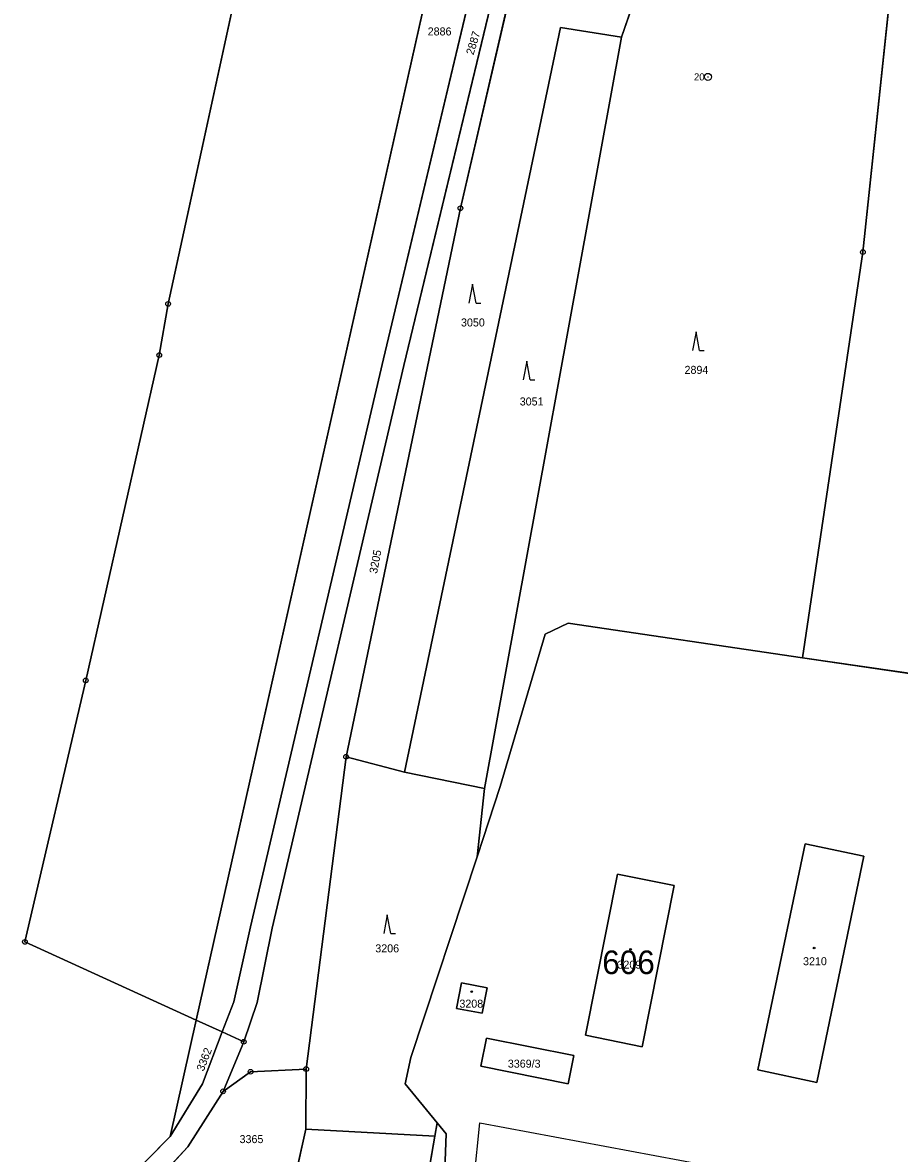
# Model space of a CAD drawing. Extents: x -689422 to -685210, y -987725 to -982160.
# Drawn here: x -688196.3 to -688010, y -986923.9 to -986683.7 of the extents above; entities that cross this region are included whole.
import ezdxf

# ---------------------------------------------------------------- set-up
doc = ezdxf.new("R2010")
doc.units = 0
for name, color, linetype in [('KN_Budovy', 7, 'Continuous'), ('KN_Budovy_cisla_domovni', 7, 'Continuous'), ('KN_Hranice_parcel', 7, 'Continuous'), ('KN_Hranice_parcel_vnitrni_kresba', 7, 'Continuous'), ('KN_Parcelni cisla', 7, 'Continuous'), ('KN_Polygon parcely', 7, 'Continuous'), ('KN_POZEMKY_LESNI POZEMEK', 7, 'Continuous'), ('KN_POZEMKY_ORNA PUDA', 7, 'Continuous'), ('KN_POZEMKY_OSTATNI PLOCHA', 7, 'Continuous'), ('KN_POZEMKY_ZASTAVENA PLOCHA', 7, 'Continuous'), ('KN_VYUZITI_17_ostatni plocha_ostatni komunikace', 7, 'Continuous'), ('KN_VYUZITI_23_ostatni plocha_manipulacni plocha', 7, 'Continuous'), ('KN_VYUZITI_26_ostatni plocha_jina plocha', 7, 'Continuous'), ('KN_Značky bodu BP', 7, 'Continuous'), ('KN_Značky budov', 7, 'Continuous'), ('KN_Značky kultur', 7, 'Continuous')]:
    doc.layers.add(name, color=color, linetype=linetype)

msp = doc.modelspace()

# ---------------------------------------------------------------- linework, layer by layer
at = {"layer": 'KN_Budovy'}
for points in [[(-688027.49, -986908.86), (-688017.55, -986860.75), (-688030.03, -986858.17), (-688040.05, -986906.21)], [(-688069.91, -986864.6), (-688076.68, -986898.8), (-688064.67, -986901.32), (-688057.85, -986866.99)], [(-688103.01, -986887.69), (-688104.12, -986893.15), (-688098.66, -986894.12), (-688097.6, -986888.77)]]:
    msp.add_lwpolyline(points, close=True, dxfattribs=at)
at = {"layer": 'KN_Hranice_parcel'}
for p, q in [((-688159.4, -986895.61), (-688054.13, -986426.81)), ((-688063.02, -986669.39), (-688069.02, -986686.77)), ((-688011.67, -986674.75), (-688017.74, -986732.42)), ((-688069.02, -986686.77), (-688098.17, -986846.39)), ((-688017.74, -986732.42), (-688030.54, -986818.6)), ((-688080.39, -986811.27), (-688030.54, -986818.6)), ((-688030.54, -986818.6), (-687921.47, -986834.64)), ((-688127.55, -986839.67), (-688136.03, -986906.02)), ((-688127.55, -986839.67), (-688115.17, -986842.96)), ((-688115.17, -986842.96), (-688098.17, -986846.39)), ((-688099.71, -986860.89), (-688094.78, -986845.97)), ((-688098.17, -986846.39), (-688099.71, -986860.89)), ((-688113.79, -986903.54), (-688099.71, -986860.89)), ((-688164.95, -986920.32), (-688159.4, -986895.61)), ((-688159.4, -986895.61), (-688153.85, -986898.14)), ((-688153.85, -986898.14), (-688149.3, -986900.22)), ((-688149.3, -986900.22), (-688153.68, -986910.75)), ((-688136.03, -986906.02), (-688136.11, -986918.82)), ((-688108.67, -986920.25), (-688108.19, -986917.45)), ((-688136.11, -986918.82), (-688108.67, -986920.25)), ((-688108.67, -986920.25), (-688122.47, -987000.06))]:
    msp.add_line(p, q, dxfattribs=at)
for points in [[(-688159.4, -986895.61), (-688195.78, -986878.99), (-688182.85, -986823.42), (-688167.24, -986754.29), (-688165.37, -986743.42), (-688139.35, -986623.85), (-688109.82, -986514.74), (-688083.69, -986418.21), (-688054.13, -986426.81)], [(-688153.85, -986898.14), (-688151.4, -986891.74), (-688147.87, -986875.77), (-688119.62, -986755.13), (-688100.96, -986676.85), (-688080.88, -986596.53), (-688070.98, -986551.86), (-688053.37, -986481.38), (-688042.32, -986437.91), (-688040.63, -986430.74)], [(-688149.3, -986900.22), (-688146.47, -986891.87), (-688143.27, -986876.11), (-688115.31, -986756.51), (-688096.35, -986678.03), (-688076.79, -986597.87), (-688066.92, -986553.28), (-688049.47, -986482.89), (-688036.65, -986431.9)], [(-688089.54, -986664.62), (-688091, -986670.24), (-688103.26, -986723.09), (-688127.55, -986839.67)], [(-688115.17, -986842.96), (-688082.01, -986684.71), (-688069.02, -986686.77)], [(-688094.78, -986845.97), (-688085.26, -986813.61), (-688080.39, -986811.27)], [(-688017.55, -986860.75), (-688030.03, -986858.17), (-688040.05, -986906.21), (-688027.49, -986908.86), (-688017.55, -986860.75)], [(-688064.67, -986901.32), (-688057.85, -986866.99), (-688069.91, -986864.6), (-688076.68, -986898.8), (-688064.67, -986901.32)], [(-688103.01, -986887.69), (-688104.12, -986893.15), (-688098.66, -986894.12), (-688097.6, -986888.77), (-688103.01, -986887.69)], [(-688164.95, -986920.32), (-688158.09, -986909.19), (-688153.85, -986898.14)], [(-688097.69, -986899.48), (-688098.9, -986905.4), (-688080.34, -986909.15), (-688079.13, -986903.11), (-688097.69, -986899.48)], [(-688108.19, -986917.45), (-688114.98, -986909.18), (-688113.79, -986903.54)], [(-688153.68, -986910.75), (-688147.85, -986906.59), (-688136.03, -986906.02)], [(-688189.3, -986941.47), (-688172.33, -986934.61), (-688161.2, -986922.54), (-688153.68, -986910.75)], [(-688115.39, -987004.23), (-688107.71, -986957.91), (-688106.29, -986919.76), (-688108.19, -986917.45)], [(-688193.03, -986937.49), (-688175.31, -986930.89), (-688164.95, -986920.32)], [(-688144.21, -986962.1), (-688141.1, -986941.33), (-688136.11, -986918.82)]]:
    msp.add_lwpolyline(points, dxfattribs=at)
at = {"layer": 'KN_Hranice_parcel_vnitrni_kresba'}
for p, q in [((-688108.07, -987008.55), (-688099.13, -986917.41)), ((-688099.13, -986917.41), (-687943.29, -986946.49))]:
    msp.add_line(p, q, dxfattribs=at)
at = {"layer": 'KN_Polygon parcely'}
for points in [[(-688175.31, -986930.89), (-688164.95, -986920.32), (-688159.4, -986895.61), (-688195.78, -986878.99), (-688182.85, -986823.42), (-688167.24, -986754.29), (-688165.37, -986743.42), (-688139.35, -986623.85), (-688109.82, -986514.74), (-688083.69, -986418.21), (-688054.13, -986426.81), (-687983.51, -986112.31), (-687977.17, -986084.07), (-687905.28, -985782.43)], [(-687738.9, -987010.24), (-687777.85, -986868.06), (-687801.59, -986853.04), (-687857.29, -986844.48), (-687917.71, -986835.19), (-687921.47, -986834.64), (-688030.54, -986818.6), (-688080.39, -986811.27), (-688085.26, -986813.61), (-688094.78, -986845.97), (-688099.71, -986860.89), (-688113.79, -986903.54), (-688114.98, -986909.18), (-688108.19, -986917.45), (-688106.29, -986919.76), (-688107.71, -986957.91)]]:
    msp.add_lwpolyline(points, dxfattribs=at)
for points in [[(-688054.13, -986426.81), (-688083.69, -986418.21), (-688109.82, -986514.74), (-688139.35, -986623.85), (-688165.37, -986743.42), (-688167.24, -986754.29), (-688182.85, -986823.42), (-688195.78, -986878.99), (-688159.4, -986895.61)], [(-688080.88, -986596.53), (-688070.98, -986551.86), (-688053.37, -986481.38), (-688042.32, -986437.91), (-688040.63, -986430.74), (-688054.13, -986426.81), (-688159.4, -986895.61), (-688153.85, -986898.14), (-688151.4, -986891.74), (-688147.87, -986875.77), (-688119.62, -986755.13), (-688100.96, -986676.85)], [(-688036.65, -986431.9), (-688040.63, -986430.74), (-688042.32, -986437.91), (-688053.37, -986481.38), (-688070.98, -986551.86), (-688080.88, -986596.53), (-688100.96, -986676.85), (-688119.62, -986755.13), (-688147.87, -986875.77), (-688151.4, -986891.74), (-688153.85, -986898.14), (-688149.3, -986900.22), (-688146.47, -986891.87), (-688143.27, -986876.11), (-688115.31, -986756.51), (-688096.35, -986678.03), (-688076.79, -986597.87), (-688066.92, -986553.28), (-688049.47, -986482.89)], [(-688136.03, -986906.02), (-688127.55, -986839.67), (-688103.26, -986723.09), (-688091, -986670.24), (-688089.54, -986664.62), (-688058, -986528.56), (-688049.36, -986498.45), (-688032.72, -986433.04), (-688036.65, -986431.9), (-688049.47, -986482.89), (-688066.92, -986553.28), (-688076.79, -986597.87), (-688096.35, -986678.03), (-688115.31, -986756.51), (-688143.27, -986876.11), (-688146.47, -986891.87), (-688149.3, -986900.22), (-688153.68, -986910.75), (-688147.85, -986906.59)], [(-688103.26, -986723.09), (-688127.55, -986839.67), (-688115.17, -986842.96), (-688082.01, -986684.71), (-688069.02, -986686.77), (-688063.02, -986669.39), (-688089.54, -986664.62), (-688091, -986670.24)], [(-688085.26, -986813.61), (-688080.39, -986811.27), (-688030.54, -986818.6), (-688017.74, -986732.42), (-688011.67, -986674.75), (-688039.58, -986673.59), (-688063.02, -986669.39), (-688069.02, -986686.77), (-688098.17, -986846.39), (-688099.71, -986860.89), (-688094.78, -986845.97)], [(-687920.87, -986800.86), (-687926.5, -986779.93), (-687934.33, -986763.83), (-687962.23, -986719.38), (-687985.54, -986690.08), (-687997.98, -986679.13), (-687998.95, -986675.6), (-688011.67, -986674.75), (-688017.74, -986732.42), (-688030.54, -986818.6), (-687921.47, -986834.64), (-687920.71, -986829.52)], [(-688115.17, -986842.96), (-688098.17, -986846.39), (-688069.02, -986686.77), (-688082.01, -986684.71)], [(-688136.11, -986918.82), (-688108.67, -986920.25), (-688108.19, -986917.45), (-688114.98, -986909.18), (-688113.79, -986903.54), (-688099.71, -986860.89), (-688098.17, -986846.39), (-688115.17, -986842.96), (-688127.55, -986839.67), (-688136.03, -986906.02)], [(-688017.55, -986860.75), (-688027.49, -986908.86), (-688040.05, -986906.21), (-688030.03, -986858.17)], [(-688017.55, -986860.75), (-688030.03, -986858.17), (-688040.05, -986906.21), (-688027.49, -986908.86)], [(-688064.67, -986901.32), (-688076.68, -986898.8), (-688069.91, -986864.6), (-688057.85, -986866.99)], [(-688064.67, -986901.32), (-688057.85, -986866.99), (-688069.91, -986864.6), (-688076.68, -986898.8)], [(-688103.01, -986887.69), (-688097.6, -986888.77), (-688098.66, -986894.12), (-688104.12, -986893.15)], [(-688103.01, -986887.69), (-688104.12, -986893.15), (-688098.66, -986894.12), (-688097.6, -986888.77)], [(-688158.09, -986909.19), (-688153.85, -986898.14), (-688159.4, -986895.61), (-688164.95, -986920.32)], [(-688153.85, -986898.14), (-688158.09, -986909.19), (-688164.95, -986920.32), (-688175.31, -986930.89), (-688193.03, -986937.49), (-688189.3, -986941.47), (-688172.33, -986934.61), (-688161.2, -986922.54), (-688153.68, -986910.75), (-688149.3, -986900.22)], [(-688097.69, -986899.48), (-688098.9, -986905.4), (-688080.34, -986909.15), (-688079.13, -986903.11)], [(-688097.69, -986899.48), (-688079.13, -986903.11), (-688080.34, -986909.15), (-688098.9, -986905.4)], [(-688172.5, -986957.86), (-688159.99, -986972.11), (-688144.21, -986962.1), (-688141.1, -986941.33), (-688136.11, -986918.82), (-688136.03, -986906.02), (-688147.85, -986906.59), (-688153.68, -986910.75), (-688161.2, -986922.54), (-688172.33, -986934.61), (-688189.3, -986941.47)], [(-688122.47, -987000.06), (-688115.39, -987004.23), (-688107.71, -986957.91), (-688106.29, -986919.76), (-688108.19, -986917.45), (-688108.67, -986920.25)], [(-688137.49, -986990.9), (-688122.47, -987000.06), (-688108.67, -986920.25), (-688136.11, -986918.82), (-688141.1, -986941.33), (-688144.21, -986962.1), (-688146.94, -986984.31)]]:
    msp.add_lwpolyline(points, close=True, dxfattribs=at)
at = {"layer": 'KN_POZEMKY_LESNI POZEMEK'}
for p, q in [((-688103.26, -986723.09), (-688091, -986670.24)), ((-688063.02, -986669.39), (-688069.02, -986686.77)), ((-688069.02, -986686.77), (-688063.02, -986669.39)), ((-688017.74, -986732.42), (-688011.67, -986674.75)), ((-688011.67, -986674.75), (-688017.74, -986732.42)), ((-688115.17, -986842.96), (-688082.01, -986684.71)), ((-688082.01, -986684.71), (-688115.17, -986842.96)), ((-688082.01, -986684.71), (-688069.02, -986686.77)), ((-688069.02, -986686.77), (-688082.01, -986684.71)), ((-688069.02, -986686.77), (-688098.17, -986846.39)), ((-688098.17, -986846.39), (-688069.02, -986686.77)), ((-688127.55, -986839.67), (-688103.26, -986723.09)), ((-688030.54, -986818.6), (-688017.74, -986732.42)), ((-688017.74, -986732.42), (-688030.54, -986818.6)), ((-688085.26, -986813.61), (-688080.39, -986811.27)), ((-688080.39, -986811.27), (-688085.26, -986813.61)), ((-688080.39, -986811.27), (-688030.54, -986818.6)), ((-688030.54, -986818.6), (-688080.39, -986811.27)), ((-688094.78, -986845.97), (-688085.26, -986813.61)), ((-688085.26, -986813.61), (-688094.78, -986845.97)), ((-688030.54, -986818.6), (-687921.47, -986834.64)), ((-687921.47, -986834.64), (-688030.54, -986818.6)), ((-688136.03, -986906.02), (-688127.55, -986839.67)), ((-688115.17, -986842.96), (-688127.55, -986839.67)), ((-688127.55, -986839.67), (-688115.17, -986842.96)), ((-688098.17, -986846.39), (-688115.17, -986842.96)), ((-688115.17, -986842.96), (-688098.17, -986846.39)), ((-688099.71, -986860.89), (-688094.78, -986845.97)), ((-688094.78, -986845.97), (-688099.71, -986860.89)), ((-688098.17, -986846.39), (-688099.71, -986860.89)), ((-688099.71, -986860.89), (-688098.17, -986846.39)), ((-688030.03, -986858.17), (-688040.05, -986906.21)), ((-688017.55, -986860.75), (-688030.03, -986858.17)), ((-688113.79, -986903.54), (-688099.71, -986860.89)), ((-688099.71, -986860.89), (-688113.79, -986903.54)), ((-688027.49, -986908.86), (-688017.55, -986860.75)), ((-688069.91, -986864.6), (-688076.68, -986898.8)), ((-688057.85, -986866.99), (-688069.91, -986864.6)), ((-688064.67, -986901.32), (-688057.85, -986866.99)), ((-688103.01, -986887.69), (-688104.12, -986893.15)), ((-688097.6, -986888.77), (-688103.01, -986887.69)), ((-688098.66, -986894.12), (-688097.6, -986888.77)), ((-688104.12, -986893.15), (-688098.66, -986894.12)), ((-688097.69, -986899.48), (-688098.9, -986905.4)), ((-688079.13, -986903.11), (-688097.69, -986899.48)), ((-688076.68, -986898.8), (-688064.67, -986901.32)), ((-688114.98, -986909.18), (-688113.79, -986903.54)), ((-688113.79, -986903.54), (-688114.98, -986909.18)), ((-688080.34, -986909.15), (-688079.13, -986903.11)), ((-688098.9, -986905.4), (-688080.34, -986909.15)), ((-688136.11, -986918.82), (-688136.03, -986906.02)), ((-688040.05, -986906.21), (-688027.49, -986908.86)), ((-688108.19, -986917.45), (-688114.98, -986909.18)), ((-688114.98, -986909.18), (-688108.19, -986917.45)), ((-688108.19, -986917.45), (-688108.67, -986920.25)), ((-688108.67, -986920.25), (-688108.19, -986917.45)), ((-688106.29, -986919.76), (-688108.19, -986917.45)), ((-688108.19, -986917.45), (-688106.29, -986919.76)), ((-688141.1, -986941.33), (-688136.11, -986918.82)), ((-688108.67, -986920.25), (-688136.11, -986918.82)), ((-688136.11, -986918.82), (-688108.67, -986920.25)), ((-688122.47, -987000.06), (-688108.67, -986920.25)), ((-688108.67, -986920.25), (-688122.47, -987000.06)), ((-688107.71, -986957.91), (-688106.29, -986919.76)), ((-688106.29, -986919.76), (-688107.71, -986957.91))]:
    msp.add_line(p, q, dxfattribs=at)
at = {"layer": 'KN_POZEMKY_ORNA PUDA'}
for p, q in [((-688159.4, -986895.61), (-688054.13, -986426.81)), ((-688091, -986670.24), (-688103.26, -986723.09)), ((-688100.96, -986676.85), (-688119.62, -986755.13)), ((-688115.31, -986756.51), (-688096.35, -986678.03)), ((-688103.26, -986723.09), (-688127.55, -986839.67)), ((-688119.62, -986755.13), (-688147.87, -986875.77)), ((-688143.27, -986876.11), (-688115.31, -986756.51)), ((-688127.55, -986839.67), (-688136.03, -986906.02)), ((-688147.87, -986875.77), (-688151.4, -986891.74)), ((-688146.47, -986891.87), (-688143.27, -986876.11)), ((-688151.4, -986891.74), (-688153.85, -986898.14)), ((-688149.3, -986900.22), (-688146.47, -986891.87)), ((-688164.95, -986920.32), (-688159.4, -986895.61)), ((-688153.85, -986898.14), (-688159.4, -986895.61)), ((-688159.4, -986895.61), (-688153.85, -986898.14)), ((-688153.85, -986898.14), (-688158.09, -986909.19)), ((-688153.68, -986910.75), (-688149.3, -986900.22)), ((-688147.85, -986906.59), (-688153.68, -986910.75)), ((-688136.03, -986906.02), (-688147.85, -986906.59)), ((-688158.09, -986909.19), (-688164.95, -986920.32))]:
    msp.add_line(p, q, dxfattribs=at)
at = {"layer": 'KN_POZEMKY_OSTATNI PLOCHA'}
for p, q in [((-688054.13, -986426.81), (-688159.4, -986895.61)), ((-688165.37, -986743.42), (-688139.35, -986623.85)), ((-688139.35, -986623.85), (-688165.37, -986743.42)), ((-688119.62, -986755.13), (-688100.96, -986676.85)), ((-688096.35, -986678.03), (-688115.31, -986756.51)), ((-688167.24, -986754.29), (-688165.37, -986743.42)), ((-688165.37, -986743.42), (-688167.24, -986754.29)), ((-688182.85, -986823.42), (-688167.24, -986754.29)), ((-688167.24, -986754.29), (-688182.85, -986823.42)), ((-688147.87, -986875.77), (-688119.62, -986755.13)), ((-688115.31, -986756.51), (-688143.27, -986876.11)), ((-688195.78, -986878.99), (-688182.85, -986823.42)), ((-688182.85, -986823.42), (-688195.78, -986878.99)), ((-688151.4, -986891.74), (-688147.87, -986875.77)), ((-688143.27, -986876.11), (-688146.47, -986891.87)), ((-688159.4, -986895.61), (-688195.78, -986878.99)), ((-688195.78, -986878.99), (-688159.4, -986895.61)), ((-688153.85, -986898.14), (-688151.4, -986891.74)), ((-688146.47, -986891.87), (-688149.3, -986900.22)), ((-688159.4, -986895.61), (-688164.95, -986920.32)), ((-688158.09, -986909.19), (-688153.85, -986898.14)), ((-688149.3, -986900.22), (-688153.85, -986898.14)), ((-688153.85, -986898.14), (-688149.3, -986900.22)), ((-688149.3, -986900.22), (-688153.68, -986910.75)), ((-688098.9, -986905.4), (-688097.69, -986899.48)), ((-688097.69, -986899.48), (-688079.13, -986903.11)), ((-688079.13, -986903.11), (-688080.34, -986909.15)), ((-688080.34, -986909.15), (-688098.9, -986905.4)), ((-688153.68, -986910.75), (-688147.85, -986906.59)), ((-688147.85, -986906.59), (-688136.03, -986906.02)), ((-688136.03, -986906.02), (-688136.11, -986918.82)), ((-688164.95, -986920.32), (-688158.09, -986909.19)), ((-688153.68, -986910.75), (-688161.2, -986922.54)), ((-688161.2, -986922.54), (-688153.68, -986910.75)), ((-688175.31, -986930.89), (-688164.95, -986920.32)), ((-688164.95, -986920.32), (-688175.31, -986930.89)), ((-688136.11, -986918.82), (-688141.1, -986941.33)), ((-688161.2, -986922.54), (-688172.33, -986934.61)), ((-688172.33, -986934.61), (-688161.2, -986922.54))]:
    msp.add_line(p, q, dxfattribs=at)
at = {"layer": 'KN_POZEMKY_ZASTAVENA PLOCHA'}
for p, q in [((-688040.05, -986906.21), (-688030.03, -986858.17)), ((-688030.03, -986858.17), (-688017.55, -986860.75)), ((-688017.55, -986860.75), (-688027.49, -986908.86)), ((-688076.68, -986898.8), (-688069.91, -986864.6)), ((-688069.91, -986864.6), (-688057.85, -986866.99)), ((-688057.85, -986866.99), (-688064.67, -986901.32)), ((-688104.12, -986893.15), (-688103.01, -986887.69)), ((-688103.01, -986887.69), (-688097.6, -986888.77)), ((-688097.6, -986888.77), (-688098.66, -986894.12)), ((-688098.66, -986894.12), (-688104.12, -986893.15)), ((-688064.67, -986901.32), (-688076.68, -986898.8)), ((-688027.49, -986908.86), (-688040.05, -986906.21))]:
    msp.add_line(p, q, dxfattribs=at)
at = {"layer": 'KN_VYUZITI_17_ostatni plocha_ostatni komunikace'}
for p, q in [((-688119.62, -986755.13), (-688100.96, -986676.85)), ((-688096.35, -986678.03), (-688115.31, -986756.51)), ((-688147.87, -986875.77), (-688119.62, -986755.13)), ((-688115.31, -986756.51), (-688143.27, -986876.11)), ((-688151.4, -986891.74), (-688147.87, -986875.77)), ((-688143.27, -986876.11), (-688146.47, -986891.87)), ((-688153.85, -986898.14), (-688151.4, -986891.74)), ((-688146.47, -986891.87), (-688149.3, -986900.22)), ((-688158.09, -986909.19), (-688153.85, -986898.14)), ((-688149.3, -986900.22), (-688153.85, -986898.14)), ((-688153.85, -986898.14), (-688149.3, -986900.22)), ((-688149.3, -986900.22), (-688153.68, -986910.75)), ((-688164.95, -986920.32), (-688158.09, -986909.19)), ((-688153.68, -986910.75), (-688161.2, -986922.54)), ((-688175.31, -986930.89), (-688164.95, -986920.32)), ((-688161.2, -986922.54), (-688172.33, -986934.61))]:
    msp.add_line(p, q, dxfattribs=at)
at = {"layer": 'KN_VYUZITI_23_ostatni plocha_manipulacni plocha'}
for p, q in [((-688054.13, -986426.81), (-688159.4, -986895.61)), ((-688165.37, -986743.42), (-688139.35, -986623.85)), ((-688139.35, -986623.85), (-688165.37, -986743.42)), ((-688167.24, -986754.29), (-688165.37, -986743.42)), ((-688165.37, -986743.42), (-688167.24, -986754.29)), ((-688182.85, -986823.42), (-688167.24, -986754.29)), ((-688167.24, -986754.29), (-688182.85, -986823.42)), ((-688195.78, -986878.99), (-688182.85, -986823.42)), ((-688182.85, -986823.42), (-688195.78, -986878.99)), ((-688159.4, -986895.61), (-688195.78, -986878.99)), ((-688195.78, -986878.99), (-688159.4, -986895.61)), ((-688159.4, -986895.61), (-688164.95, -986920.32)), ((-688153.68, -986910.75), (-688147.85, -986906.59)), ((-688147.85, -986906.59), (-688136.03, -986906.02)), ((-688136.03, -986906.02), (-688136.11, -986918.82)), ((-688161.2, -986922.54), (-688153.68, -986910.75)), ((-688164.95, -986920.32), (-688175.31, -986930.89)), ((-688136.11, -986918.82), (-688141.1, -986941.33)), ((-688172.33, -986934.61), (-688161.2, -986922.54))]:
    msp.add_line(p, q, dxfattribs=at)
at = {"layer": 'KN_VYUZITI_26_ostatni plocha_jina plocha'}
for p, q in [((-688098.9, -986905.4), (-688097.69, -986899.48)), ((-688097.69, -986899.48), (-688079.13, -986903.11)), ((-688079.13, -986903.11), (-688080.34, -986909.15)), ((-688080.34, -986909.15), (-688098.9, -986905.4))]:
    msp.add_line(p, q, dxfattribs=at)
at = {"layer": 'KN_Značky bodu BP'}
for centre, radius in [((-688050.66, -986695.19), 0.75), ((-688050.66, -986695.19), 0.03), ((-688103.26, -986723.09), 0.5), ((-688103.26, -986723.09), 0.0303), ((-688017.74, -986732.42), 0.5), ((-688017.74, -986732.42), 0.0303), ((-688165.37, -986743.42), 0.5), ((-688165.37, -986743.42), 0.0303), ((-688167.24, -986754.29), 0.5), ((-688167.24, -986754.29), 0.0303), ((-688182.85, -986823.42), 0.5), ((-688182.85, -986823.42), 0.0303), ((-688127.55, -986839.67), 0.5), ((-688127.55, -986839.67), 0.0303), ((-688195.78, -986878.99), 0.5), ((-688195.78, -986878.99), 0.0303), ((-688149.3, -986900.22), 0.5), ((-688149.3, -986900.22), 0.0303), ((-688136.03, -986906.02), 0.5), ((-688147.85, -986906.59), 0.5), ((-688147.85, -986906.59), 0.0303), ((-688136.03, -986906.02), 0.0303), ((-688153.68, -986910.75), 0.5), ((-688153.68, -986910.75), 0.0303)]:
    msp.add_circle(centre, radius, dxfattribs=at)
at = {"layer": 'KN_Značky budov'}
for centre in [(-688067.1, -986880.57), (-688028.1, -986880.3), (-688100.85, -986889.57)]:
    msp.add_circle(centre, 0.175, dxfattribs=at)
at = {"layer": 'KN_Značky kultur'}
for p, q in [((-688100.69, -986739.26), (-688101.44, -986743.26)), ((-688099.94, -986743.26), (-688100.69, -986739.26)), ((-688099.94, -986743.26), (-688098.94, -986743.26)), ((-688053.19, -986749.34), (-688053.94, -986753.34)), ((-688052.44, -986753.34), (-688053.19, -986749.34)), ((-688052.44, -986753.34), (-688051.44, -986753.34)), ((-688089.17, -986755.57), (-688089.92, -986759.57)), ((-688088.42, -986759.57), (-688089.17, -986755.57)), ((-688088.42, -986759.57), (-688087.42, -986759.57)), ((-688118.81, -986873.22), (-688119.56, -986877.22)), ((-688118.06, -986877.22), (-688118.81, -986873.22)), ((-688118.06, -986877.22), (-688117.06, -986877.22))]:
    msp.add_line(p, q, dxfattribs=at)

# ---------------------------------------------------------------- texts
at = {"layer": 'KN_Budovy_cisla_domovni'}
msp.add_text('606', height=5, dxfattribs=at).set_placement((-688073.11, -986885.83))
at = {"layer": 'KN_Parcelni cisla'}
for s, p in [('2886', (-688110.21, -986686.38)), ('3050', (-688103.13, -986748.22)), ('2894', (-688055.63, -986758.29)), ('3051', (-688090.65, -986765.01)), ('3206', (-688121.34, -986881.22)), ('3209', (-688069.88, -986884.69)), ('3210', (-688030.45, -986883.95)), ('3208', (-688103.47, -986892.97)), ('3369/3', (-688093.18, -986905.72)), ('3365', (-688150.18, -986921.75))]:
    msp.add_text(s, height=1.7, dxfattribs=at).set_placement(p)
for s, rotation, p in [('2887', 73, (-688100.49, -986690.65)), ('3205', 79, (-688120.98, -986800.83)), ('3362', 69, (-688157.82, -986906.62))]:
    msp.add_text(s, height=1.7, rotation=rotation, dxfattribs=at).set_placement(p)
at = {"layer": 'KN_Značky bodu BP'}
msp.add_text('20', height=1.5, dxfattribs=at).set_placement((-688053.62, -986695.94))

doc.saveas('drawing.dxf')
